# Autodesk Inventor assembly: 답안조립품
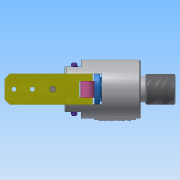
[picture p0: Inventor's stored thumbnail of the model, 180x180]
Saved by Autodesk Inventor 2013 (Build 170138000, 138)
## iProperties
Created: 2019-02
Part Number: 답안조립품
Document SubType Name: Assembly
Designer: Administrator
Author: Administrator
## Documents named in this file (11)
- C:\Users\Administrator\Desktop\490207V1013\답안조립품.iam
- C:\Users\Administrator\Desktop\490207V1013\본체.ipt
- C:\Users\Administrator\Desktop\490207V1013\E-링.ipt
- C:\Users\Administrator\Desktop\490207V1013\O-링.ipt
- C:\Users\Administrator\Desktop\490207V1013\가이드핀.ipt
- C:\Users\Administrator\Desktop\490207V1013\부시.ipt
- C:\Users\Administrator\Desktop\490207V1013\스프링.ipt
- C:\Users\Administrator\Desktop\490207V1013\평행핀 6x28.ipt
- C:\Users\Administrator\Desktop\490207V1013\피스톤.ipt
- C:\Users\Administrator\Desktop\490207V1013\핀.ipt
- C:\Users\Administrator\Desktop\490207V1013\핑거.ipt
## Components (13 placed, 6 different names)
1. E-링:1
2. O-링:1
3. 가이드핀:1
4. 피스톤:1
5. 핀:1
6. 핑거:1
7. 핑거:2
8. 가이드핀:2
9. O-링:2
10. 핀:2
11. E-링:2
12. E-링:3
13. E-링:4
